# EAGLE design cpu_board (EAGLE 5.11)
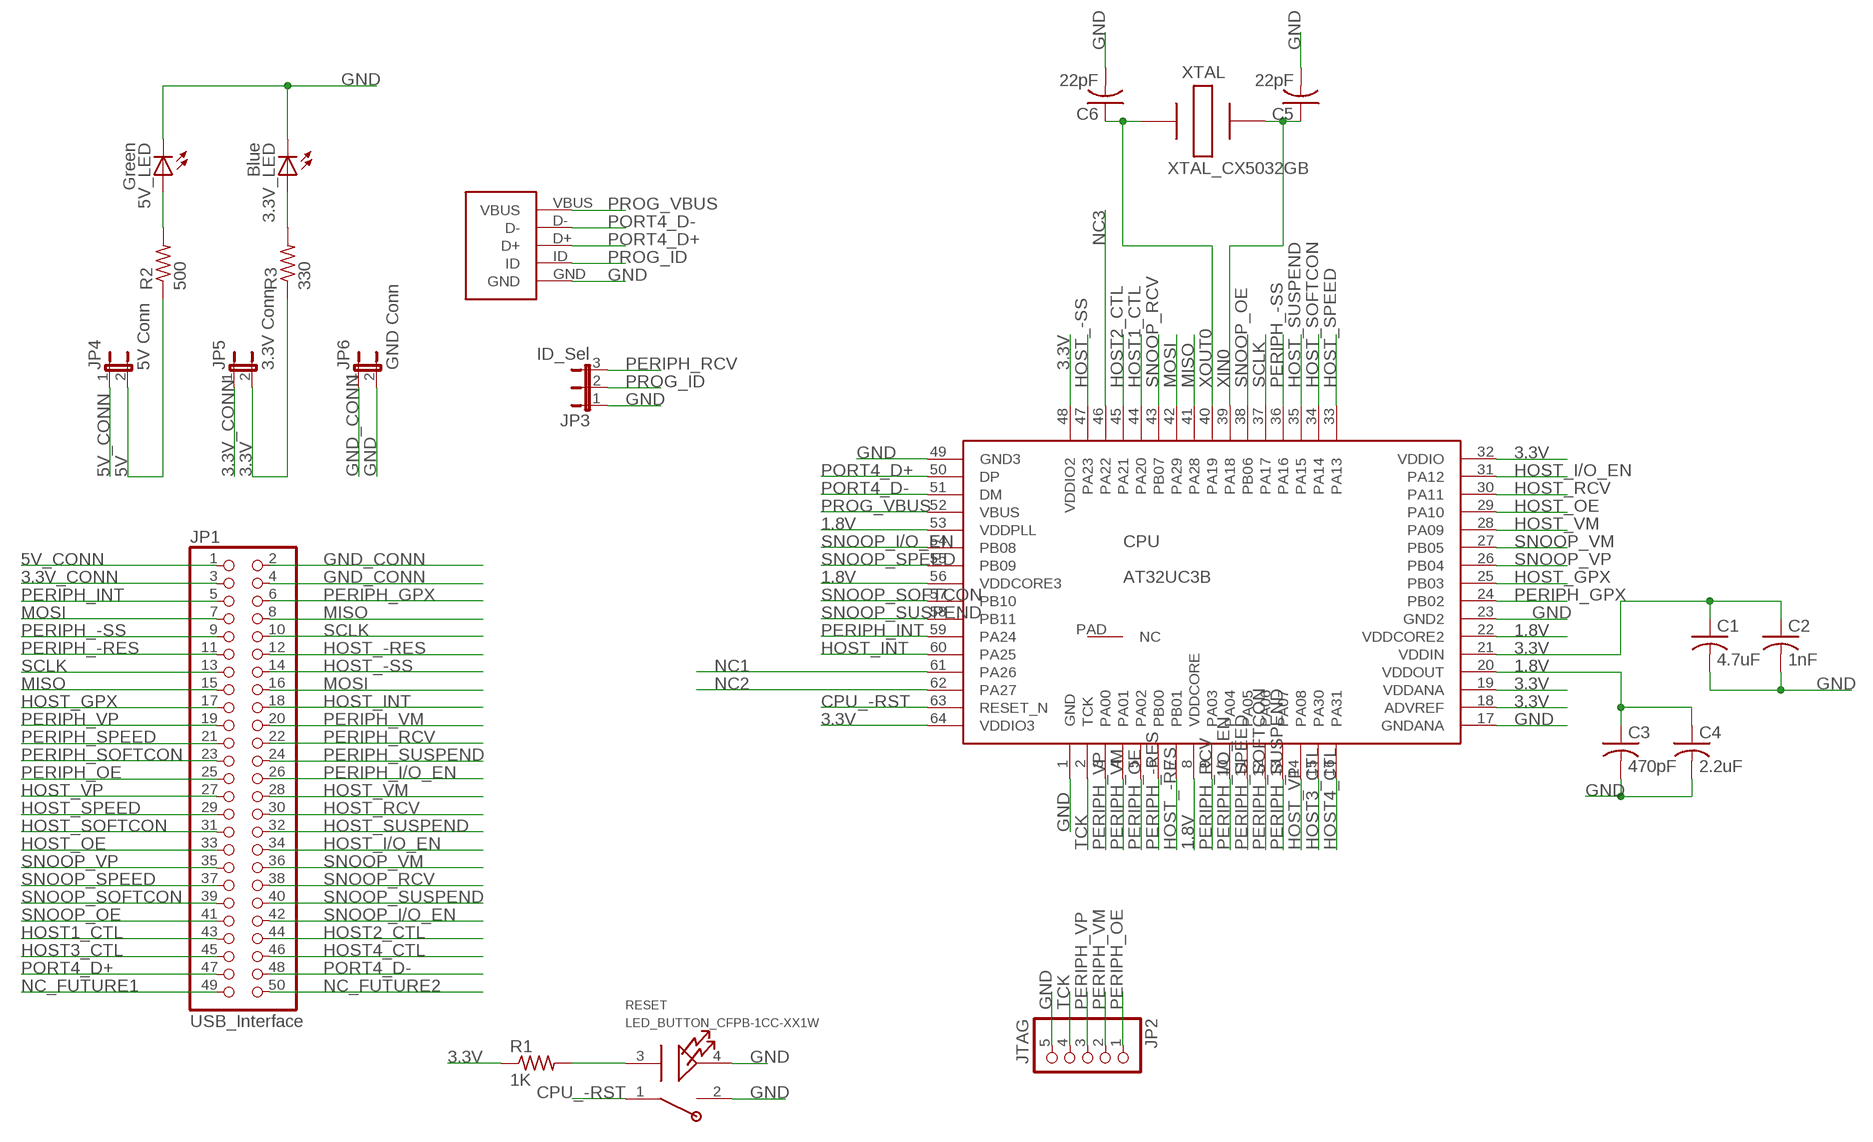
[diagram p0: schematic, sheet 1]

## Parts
3.3V_LED  Blue  LEDCHIP-LED0805  [CHIP-LED0805]
5V_LED  Green  LEDCHIP-LED0805  [CHIP-LED0805]
C1  4.7uF  C-USC0805  [C0805]
C2  1nF  C-USC0805  [C0805]
C3  470pF  C-USC0805  [C0805]
C4  2.2uF  C-USC0805  [C0805]
C5  22pF  C-USC0805  [C0805]
C6  22pF  C-USC0805  [C0805]
CPU  AT32UC3B  [QFN-64]
JP1  USB_Interface  PINHD-2X25/90  [2X25/90]
JP2  JTAG  PINHD-1X5  [1X05]
JP3  ID_Sel  JP2E  [JP2]
JP4  5V Conn  JP1E  [JP1]
JP5  3.3V Conn  JP1E  [JP1]
JP6  GND Conn  JP1E  [JP1]
R1  1K  R-US_R0805  [R0805]
R2  500  R-US_R0805  [R0805]
R3  330  R-US_R0805  [R0805]
RESET  LED_BUTTON_CFPB-1CC-XX1W  [CFPB-1CC-XX6W]
U$2  USB_MICRO_B_FEMALE  [USB_MICRO_B_FEMALE]
U$3  XTAL_CX5032GB  [CX5032GB]

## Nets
1.8V: C3.1 C4.1 CPU.8(VDDCORE) CPU.20(VDDOUT) CPU.22(VDDCORE2) CPU.53(VDDPLL) CPU.56(VDDCORE3)
3.3V: C1.1 C2.1 CPU.18(ADVREF) CPU.19(VDDANA) CPU.21(VDDIN) CPU.32(VDDIO) CPU.48(VDDIO2) CPU.64(VDDIO3) JP5.2 R1.1 R3.1
3.3V_CONN: JP1.3 JP5.1
5V: JP4.2 R2.1
5V_CONN: JP1.1 JP4.1
CPU_-RST: CPU.63(RESET_N) RESET.1(S1)
GND: 3.3V_LED.C 5V_LED.C C1.2 C2.2 C3.2 C4.2 C5.2 C6.2 CPU.1(GND) CPU.17(GNDANA) CPU.23(GND2) CPU.49(GND3) JP2.5 JP3.1 JP6.2 RESET.2(S2) RESET.4(K) U$2.GND
GND_CONN: JP1.2 JP1.4 JP6.1
HOST1_CTL: CPU.44(PA20) JP1.43
HOST2_CTL: CPU.45(PA21) JP1.44
HOST3_CTL: CPU.15(PA30) JP1.45
HOST4_CTL: CPU.16(PA31) JP1.46
HOST_-RES: CPU.7(PB01) JP1.12
HOST_-SS: CPU.47(PA23) JP1.14
HOST_GPX: CPU.25(PB03) JP1.17
HOST_I/O_EN: CPU.31(PA12) JP1.34
HOST_INT: CPU.60(PA25) JP1.18
HOST_OE: CPU.29(PA10) JP1.33
HOST_RCV: CPU.30(PA11) JP1.30
HOST_SOFTCON: CPU.34(PA14) JP1.31
HOST_SPEED: CPU.33(PA13) JP1.29
HOST_SUSPEND: CPU.35(PA15) JP1.32
HOST_VM: CPU.28(PA09) JP1.28
HOST_VP: CPU.14(PA08) JP1.27
MISO: CPU.41(PA28) JP1.8 JP1.15
MOSI: CPU.42(PA29) JP1.7 JP1.16
N$1: 5V_LED.A R2.2
N$2: R1.2 RESET.3(A)
N$4: 3.3V_LED.A R3.2
NC1: CPU.61(PA26)
NC2: CPU.62(PA27)
NC3: CPU.46(PA22)
NC_FUTURE1: JP1.49
NC_FUTURE2: JP1.50
PERIPH_-RES: CPU.6(PB00) JP1.11
PERIPH_-SS: CPU.36(PA16) JP1.9
PERIPH_GPX: CPU.24(PB02) JP1.6
PERIPH_I/O_EN: CPU.10(PA04) JP1.26
PERIPH_INT: CPU.59(PA24) JP1.5
PERIPH_OE: CPU.5(PA02) JP1.25 JP2.1
PERIPH_RCV: CPU.9(PA03) JP1.22 JP3.3
PERIPH_SOFTCON: CPU.12(PA06) JP1.23
PERIPH_SPEED: CPU.11(PA05) JP1.21
PERIPH_SUSPEND: CPU.13(PA07) JP1.24
PERIPH_VM: CPU.4(PA01) JP1.20 JP2.2
PERIPH_VP: CPU.3(PA00) JP1.19 JP2.3
PORT4_D+: CPU.50(DP) JP1.47 U$2.D+
PORT4_D-: CPU.51(DM) JP1.48 U$2.D-
PROG_ID: JP3.2 U$2.ID
PROG_VBUS: CPU.52(VBUS) U$2.VBUS
SCLK: CPU.37(PA17) JP1.10 JP1.13
SNOOP_I/O_EN: CPU.54(PB08) JP1.42
SNOOP_OE: CPU.38(PB06) JP1.41
SNOOP_RCV: CPU.43(PB07) JP1.38
SNOOP_SOFTCON: CPU.57(PB10) JP1.39
SNOOP_SPEED: CPU.55(PB09) JP1.37
SNOOP_SUSPEND: CPU.58(PB11) JP1.40
SNOOP_VM: CPU.27(PB05) JP1.36
SNOOP_VP: CPU.26(PB04) JP1.35
TCK: CPU.2(TCK) JP2.4
XIN0: C5.1 CPU.39(PA18) U$3.P$2
XOUT0: C6.1 CPU.40(PA19) U$3.P$1
Unconnected: CPU.PAD(NC)

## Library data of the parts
3.3V_LED 5V_LED = led:LED: LED
C1-C6 = resistor:C-US: CAPACITOR, American symbol
CPU = cpu_stuff:AT32UC3B
JP1 = pinhead:PINHD-2X25: PIN HEADER
JP2 = pinhead:PINHD-1X5: PIN HEADER
JP3 = jumper:JP2E: JUMPER
JP4-JP6 = jumper:JP1E: JUMPER
R1 = resistor:R-US_: RESISTOR, American symbol
R2 R3 = rcl:R-US_: RESISTOR, American symbol
RESET = cpu_stuff:LED_BUTTON_CFPB-1CC-XX1W
U$2 = usb:USB_MICRO_B_FEMALE
U$3 = cpu_stuff:XTAL_CX5032GB

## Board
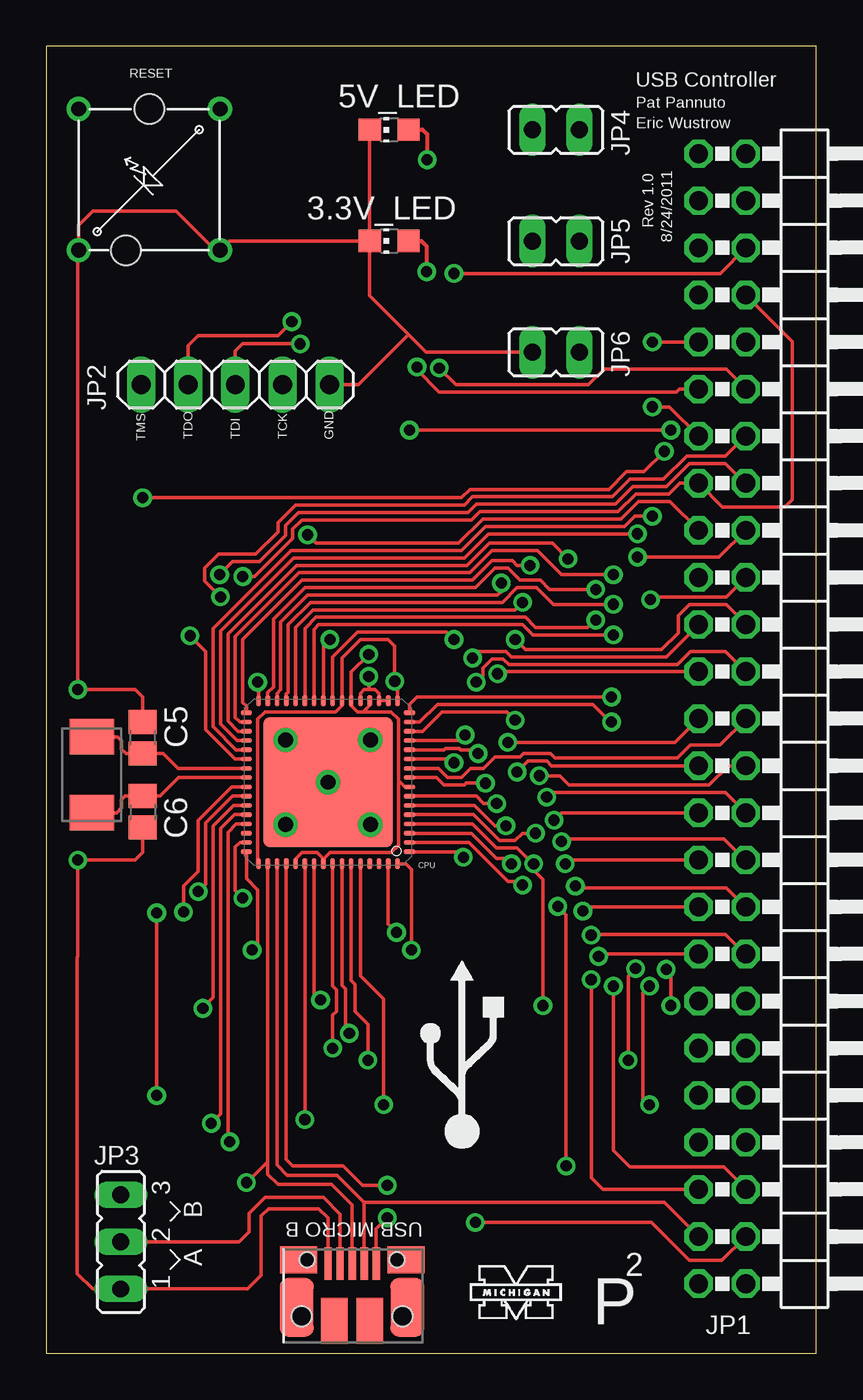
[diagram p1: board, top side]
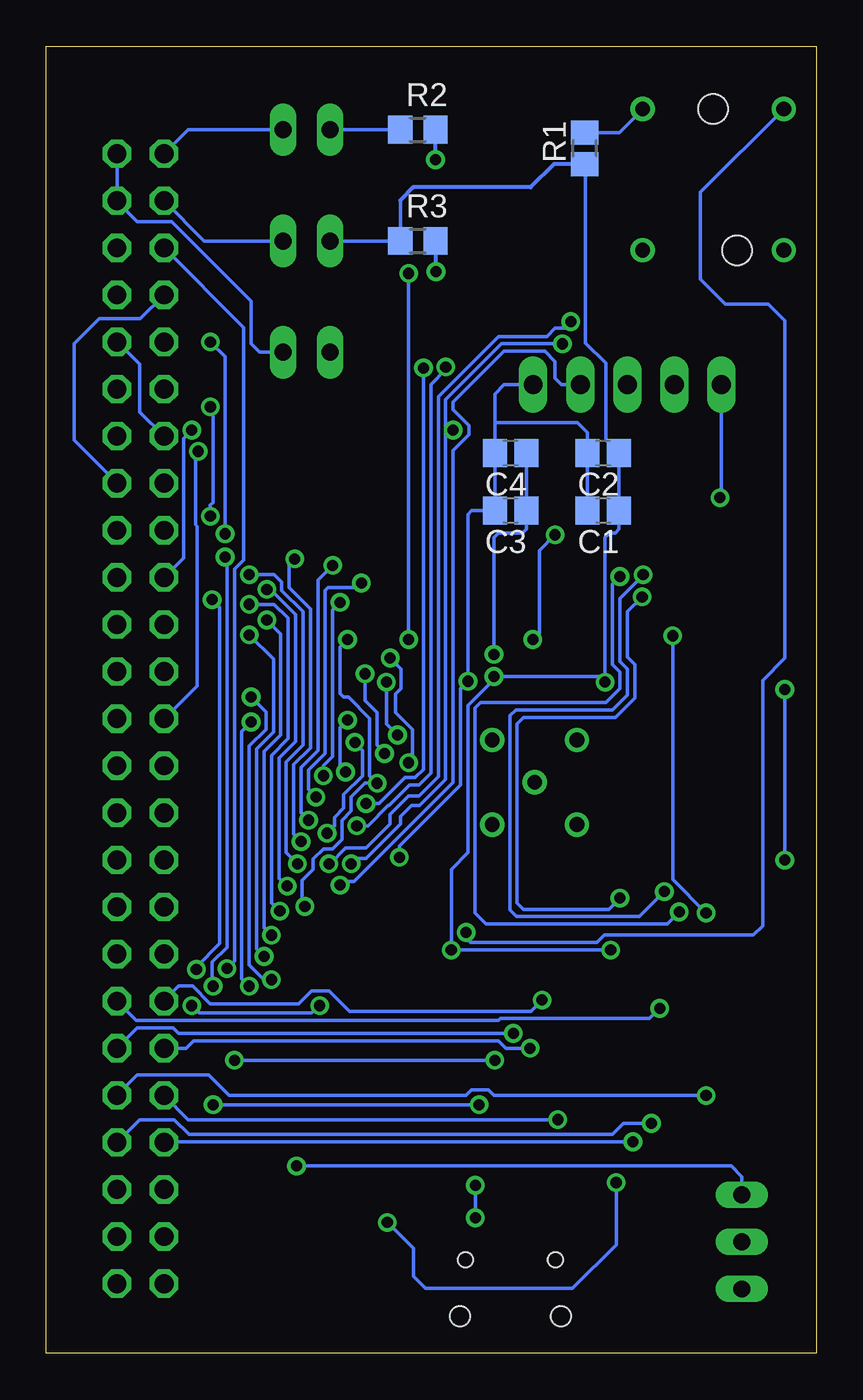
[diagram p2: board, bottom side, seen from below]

Size 41.55 x 70.5 mm. Coordinates in mm from the lower left corner, seen from the top.
Outline: 0,0 41.55,0 41.55,70.5 0,70.5 0,0
Copper layers (1*16): Top 0.035mm / dielectric 1.5mm / Bottom 0.035mm
Design rules "default *": minimum track width 7mil, minimum drill 16mil, track to track 7mil, track to pad 7mil, pad to pad 7mil, via to via 7mil, smd to smd 7mil, copper to edge 40mil, drill to drill 8mil, minimum pad ring 10mil, minimum via ring 8mil, stop-mask expansion 4mil, vias tented up to drill 0mil, thermal gap 10mil

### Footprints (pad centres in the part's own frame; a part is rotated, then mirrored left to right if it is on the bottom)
CHIP-LED0805 = smd 1.2 x 1.2: A 0,-1.05; C 0,1.05
C0805 = smd 1.3 x 1.5: 1 -0.85,0; 2 0.85,0
QFN-64 = smd 0.6 x 0.25: 1 -4.4,3.75; 2 -4.4,3.25; 3 -4.4,2.75; 4 -4.4,2.25; 5 -4.4,1.75; 6 -4.4,1.25; 7 -4.4,0.75; 8 -4.4,0.25; 9 -4.4,-0.25; 10 -4.4,-0.75; 11 -4.4,-1.25; 12 -4.4,-1.75; 13 -4.4,-2.25; 14 -4.4,-2.75; 15 -4.4,-3.25; 16 -4.4,-3.75; 33 4.4,-3.75; 34 4.4,-3.25; 35 4.4,-2.75; 36 4.4,-2.25; 37 4.4,-1.75; 38 4.4,-1.25; 39 4.4,-0.75; 40 4.4,-0.25; 41 4.4,0.25; 42 4.4,0.75; 43 4.4,1.25; 44 4.4,1.75; 45 4.4,2.25; 46 4.4,2.75; 47 4.4,3.25; 48 4.4,3.75 | smd 0.25 x 0.6: 17 -3.75,-4.4; 18 -3.25,-4.4; 19 -2.75,-4.4; 20 -2.25,-4.4; 21 -1.75,-4.4; 22 -1.25,-4.4; 23 -0.75,-4.4; 24 -0.25,-4.4; 25 0.25,-4.4; 26 0.75,-4.4; 27 1.25,-4.4; 28 1.75,-4.4; 29 2.25,-4.4; 30 2.75,-4.4; 31 3.25,-4.4; 32 3.75,-4.4; 49 3.75,4.4; 50 3.25,4.4; 51 2.75,4.4; 52 2.25,4.4; 53 1.75,4.4; 54 1.25,4.4; 55 0.75,4.4; 56 0.25,4.4; 57 -0.25,4.4; 58 -0.75,4.4; 59 -1.25,4.4; 60 -1.75,4.4; 61 -2.25,4.4; 62 -2.75,4.4; 63 -3.25,4.4; 64 -3.75,4.4 | drill 0.8 round: P$1 -2.286,2.286; P$3 -2.286,-2.286; P$4 2.286,-2.286; P$6 2.286,2.286; P$8 0,0 | smd 7 x 7: PAD 0,0
2X25/90 = drill 1.016 octagon: 1 -29.21,-6.35; 2 -29.21,-3.81; 3 -26.67,-6.35; 4 -26.67,-3.81; 5 -24.13,-6.35; 6 -24.13,-3.81; 7 -21.59,-6.35; 8 -21.59,-3.81; 9 -19.05,-6.35; 10 -19.05,-3.81; 11 -16.51,-6.35; 12 -16.51,-3.81; 13 -13.97,-6.35; 14 -13.97,-3.81; 15 -11.43,-6.35; 16 -11.43,-3.81; 17 -8.89,-6.35; 18 -8.89,-3.81; 19 -6.35,-6.35; 20 -6.35,-3.81; 21 -3.81,-6.35; 22 -3.81,-3.81; 23 -1.27,-6.35; 24 -1.27,-3.81; 25 1.27,-6.35; 26 1.27,-3.81; 27 3.81,-6.35; 28 3.81,-3.81; 29 6.35,-6.35; 30 6.35,-3.81; 31 8.89,-6.35; 32 8.89,-3.81; 33 11.43,-6.35; 34 11.43,-3.81; 35 13.97,-6.35; 36 13.97,-3.81; 37 16.51,-6.35; 38 16.51,-3.81; 39 19.05,-6.35; 40 19.05,-3.81; 41 21.59,-3.81; 42 21.59,-6.35; 43 24.13,-3.81; 44 24.13,-6.35; 45 26.67,-3.81; 46 26.67,-6.35; 47 29.21,-3.81; 48 29.21,-6.35; 49 31.75,-3.81; 50 31.75,-6.35
1X05 = drill 1.016 long: 1 -5.08,0; 2 -2.54,0; 3 0,0; 4 2.54,0; 5 5.08,0
JP2 = drill 0.914 long: 1 -2.54,0; 2 0,0; 3 2.54,0
JP1 = drill 0.914 long: 1 0,-1.27; 2 0,1.27
R0805 = smd 1.3 x 1.5: 1 -0.85,0; 2 0.85,0
R0805' = smd 1.3 x 1.5: 1 -0.95,0; 2 0.95,0
CFPB-1CC-XX6W = drill 0.8 pad 1.016 round: 1 0,7.62; 2 7.62,0; 3 7.62,7.62; 4 0,0 | hole 1.6: 2.54,0; 3.81,7.62
USB_MICRO_B_FEMALE = smd 0.4 x 1.75: D+ 0,2.825; D- 0.65,2.825; GND -1.3,2.825; ID -0.65,2.825; VBUS 1.3,2.825 | smd 1.425 x 2.5: P$6 0.963,-0.25; P$7 -0.963,-0.25 | smd 2 x 1.46: P$8 2.9,3.03; P$9 -2.9,3.03 | smd 1.825 x 3.15: P$10 2.987,0.475; P$11 -2.987,0.475 | hole 0.828: 2.425,3.03; -2.425,3.03 | hole 1.081: 2.725,0; -2.725,0
CX5032GB = smd 1.9 x 2.4: P$1 -2.05,0; P$2 2.05,0

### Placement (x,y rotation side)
3.3V_LED  18.5,60 90 top
5V_LED  18.5,66 90 top
C1  11.5,45.45 180 bottom
C2  11.5,48.55 180 bottom
C3  16.5,45.45 180 bottom
C4  16.5,48.55 180 bottom
C5  5.2,33.2 90 top
C6  5.2,29.2 270 top
CPU  15.2,30.8 180 top
JP1  41.55,35.5 270 top
JP2  10.2,52.25 0 top
JP3  4.02,6 90 top
JP4  27.5,66 90 top
JP5  27.5,60 90 top
JP6  27.5,54 90 top
R1  12.5,65 90 bottom
R2  500  [R0805']  21.5,66 0 bottom
R3  330  [R0805']  21.5,60 0 bottom
RESET  1.75,59.5 0 top
U$2  16.5,2 0 top
U$3  2.45,31.2 90 top

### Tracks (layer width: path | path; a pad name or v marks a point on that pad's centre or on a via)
1.8V  (via drill 0.6)
  Top 0.178: CPU.53 13.45,26.65 13.8,27 14.6,27 14.95,26.65 | CPU.56 14.95,26.65 | 17.15,34.65 17.45,34.95 CPU.20 | 17.15,34.65 17.1,34.6 16.8,34.6 16.45,34.95 CPU.22 16.45,36.75 v17.4,37.7 | CPU.8 19.35,30.55 19.05,30.85 | 19.05,30.85 19,30.9 19,34.2 18.6,34.6 17.2,34.6 17.15,34.65 | 14.95,26.65 15.3,27 18.6,27 19,27.4 19,30.8 19.05,30.85
  Bottom 0.178: C4.1 C3.1 15.65,44.45 15.85,44.25 17.15,44.25 17.4,44 v17.4,37.7
3.3V  (via drill 0.6)
  Top 0.178: CPU.64 19.4,26.4 19.7,26.1 v19.7,21.75 | CPU.32 11.45,36.15 v11.4,36.2 | CPU.18 CPU.19 17.95,35.6 17.75,35.8 17.4,35.8 | 17.4,35.8 17.15,35.8 16.95,35.6 CPU.21 | CPU.48 10.8,25.6 11.4,25 11.4,22.05 v11.1,21.75 | v17.4,36.5 17.4,35.8
  Bottom 0.178: JP5.2 R3.1 22.45,62.2 | R1.1 12.45,64.1 12.45,54.5 11.35,53.4 11.35,49.25 C2.1 C1.1 10.65,44.45 10.85,44.25 11.15,44.25 11.4,44 v11.4,36.2 11.7,36.5 v17.4,36.5 17.4,36.35 18.8,34.95 18.8,27 19.7,26.1 v19.7,21.75 v11.1,21.75
  Bottom 0.203: 22.45,62.2 21.76,62.89 15.42,62.89 14.16,64.15 R1.1
3.3V_CONN
  Bottom 0.178: JP1.3 33.03,60 JP5.1
5V
  Bottom 0.178: R2.1 JP4.2
5V_CONN
  Bottom 0.178: JP1.1 33.91,66 JP4.1
CPU_-RST  (via drill 0.6)
  Top 0.178: CPU.63 18.45,23.15 v18.9,22.7
  Bottom 0.178: v18.9,22.7 18.9,22.4 18.65,22.15 11.85,22.15 11.45,22.55 3.4,22.55 2.9,23.05 2.9,36.3 1.7,37.5 1.7,55.7 2.6,56.6 4.9,56.6 6.25,57.95 6.25,62.62 RESET.1
GND  (via drill 0.6)
  Top 0.178: 3.3V_LED.C 5V_LED.C | 3.3V_LED.C 9.87,60 RESET.2 9.1,59.5 7,61.6 2.5,61.6 1.75,60.85 RESET.4 1.7,59.45 v1.7,35.8 4.8,35.8 5.2,35.4 C5.2 | JP6.2 20.5,54 19.55,54.95 | 19.55,54.95 17.45,57.05 3.3V_LED.C | C6.2 5.2,27 4.8,26.6 v1.7,26.6 1.7,21.4 1.68,21.38 1.68,4.29 2.5,3.46 3.5,3.46 JP3.1 10.86,3.46 11.6,4.2 11.6,7.4 12,7.8 14.7,7.8 15.2,7.3 U$2.GND | CPU.49 11.4,26.45 11.4,34.2 11.8,34.6 15.6,34.6 15.95,34.95 CPU.23 15.95,37.5 16.95,38.5 18.45,38.5 18.8,38.15 v18.8,36.25 18.95,36.1 CPU.17 | JP2.5 16.85,52.25 19.55,54.95 | CPU.1 22.2,27.05 v22.5,26.75
  Bottom 0.178: v1.7,26.6 v1.7,35.8 | 17.35,50.2 17.35,51.75 16.85,52.25 JP2.5 | 17.35,50.2 C4.2 C3.2 18.6,45.45 18.8,45.25 v18.8,36.25 19.2,35.85 19.2,30.65 22.5,27.35 v22.5,26.75 | C1.2 C2.2 12.35,49.65 12.9,50.2 17.35,50.2
GND_CONN
  Bottom 0.178: JP1.2 JP1.4 37.74,62.14 36.65,61.05 34.8,61.05 30.5,56.75 30.5,54.45 30.05,54 JP6.1
HOST1_CTL  (via drill 0.6)
  Top 0.178: CPU.44 10.15,29.05 9.4,28.3 9.4,12.9 v8.9,12.4
  Bottom 0.178: v8.9,12.4 10.4,12.4 11,11.8 33.85,11.8 34.65,12.6 36.51,12.6 JP1.43
HOST2_CTL  (via drill 0.6)
  Top 0.178: CPU.45 10.25,28.55 9.8,28.1 9.8,11.5 v9.9,11.4
  Bottom 0.178: v9.9,11.4 35.17,11.4 JP1.44
HOST3_CTL  (via drill 0.6)
  Top 0.178: JP1.45 37.74,8.86 36.55,10.05 31.5,10.05 30.6,10.95 v30.6,19.8 | v30.5,34.05 30.45,34.05 29.5,35 21.1,35 20.15,34.05 CPU.15
  Bottom 0.178: v30.5,34.05 31,33.55 31,20.2 v30.6,19.8
HOST4_CTL  (via drill 0.6)
  Top 0.178: CPU.16 19.6,35 20,35.4 v30.5,35.4 | v29.4,20.15 29.4,9.45 30.02,8.83 JP1.46
  Bottom 0.178: v30.5,35.4 29.7,34.6 29.7,33.65 30.6,32.75 30.6,20.95 29.8,20.15 v29.4,20.15
HOST_-RES  (via drill 0.6)
  Top 0.178: CPU.7 23.2,30.05 23.6,29.65 v24.3,29.65 | JP1.12 37.74,52.06 36.7,53.1 30.1,53.1 29.25,52.25 22.1,52.25 v21.2,53.15
  Bottom 0.178: v24.3,29.65 23.6,29.65 22.2,31.05 21.65,31.05 21.2,31.5 v21.2,53.15
HOST_-SS  (via drill 0.6)
  Top 0.178: CPU.47 10.45,27.55 10.2,27.3 10.2,24.95 v10.6,24.55 | JP1.14 37.72,49.47 36.65,48.4 34.55,48.4 33.3,47.15 31.5,47.15 30.55,46.2 23,46.2 22.55,45.75 13.45,45.75 12.5,44.8 12.5,44.3 11.3,43.1 9.3,43.1 8.55,42.35 8.55,41.65 v9.4,40.8
  Bottom 0.178: v9.4,40.8 10.2,40 10.2,37.55 9.8,37.15 9.8,35.35 10.85,34.3 15.8,34.3 16.15,33.95 16.15,24.3 15.8,23.95 11.2,23.95 v10.6,24.55
HOST_GPX  (via drill 0.6)
  Top 0.178: JP1.17 33.65,45.95 31.95,45.95 31,45 23.55,45 22.25,43.7 14.55,43.7 v14.1,44.15 | v15.3,38.5 14.95,38.15 CPU.25
  Bottom 0.178: v14.1,44.15 14.95,43.3 14.95,38.85 v15.3,38.5
HOST_I/O_EN  (via drill 0.6)
  Top 0.178: JP1.34 36.7,25.1 28.65,25.1 v28.55,25.2 | v29.65,41.2 27.15,41.2 26.65,41.7 25.55,41.7 24.9,42.35 24.2,42.35 23.15,41.3 13.95,41.3 12.25,39.6 12.25,35.95 11.95,35.65 CPU.31
  Bottom 0.178: v28.55,25.2 28.6,25.2 29,25.6 29,32.1 28.1,33 28.1,39.85 29.45,41.2 v29.65,41.2
HOST_INT  (via drill 0.6)
  Top 0.178: CPU.60 16.95,20.35 18.2,19.1 v18.2,13.4 | v32.55,13.4 32.5,13.4 32.2,13.7 32.2,19.45 v32.55,19.8 | v31.9,42.95 36.3,42.95 JP1.18
  Bottom 0.178: v18.2,13.4 v32.55,13.4 | v31.9,42.95 31.8,42.85 31.8,21.9 32.6,21.1 32.6,19.85 v32.55,19.8
HOST_OE  (via drill 0.6)
  Top 0.178: JP1.33 29.17,24.07 v28.95,23.85 | v30.6,40.4 27.35,40.4 26.45,41.3 25.4,41.3 24.6,40.5 14.25,40.5 13.05,39.3 13.05,35.65 12.95,35.55 CPU.29
  Bottom 0.178: v28.95,23.85 29.4,24.3 29.4,32.25 28.5,33.15 28.5,39.65 29.25,40.4 v30.6,40.4
HOST_RCV  (via drill 0.6)
  Top 0.178: JP1.30 36.65,30.25 27.25,30.25 v27,30 | v24.55,41.55 24.55,41.1 24.35,40.9 14.1,40.9 12.65,39.45 12.65,35.8 12.45,35.6 CPU.30
  Bottom 0.178: v27,30 27.4,30.4 27.4,31.45 26.5,32.35 26.5,41.15 26.35,41.3 24.8,41.3 v24.55,41.55
HOST_SOFTCON  (via drill 0.6)
  Top 0.178: CPU.34 10.45,34.05 10.2,34.3 10.2,38.65 13.65,42.1 22.85,42.1 24.05,43.3 26.5,43.3 27.8,42 v30.6,42 | JP1.31 28.21,26.61 v28,26.4
  Bottom 0.178: v28,26.4 28.6,27 28.6,31.9 27.7,32.8 27.7,40 28.85,41.15 28.85,41.6 29.25,42 v30.6,42 | JP1.31
HOST_SPEED  (via drill 0.6)
  Top 0.178: CPU.33 10.8,34.9 10.6,35.1 10.6,38.5 13.8,41.7 23,41.7 24.05,42.75 25.15,42.75 25.4,42.5 v26.1,42.5 | JP1.29 27.8,29.15 v27.4,28.75
  Bottom 0.178: v27.4,28.75 27.8,29.15 27.8,31.6 26.9,32.5 26.9,41.7 v26.1,42.5
HOST_SUSPEND  (via drill 0.6)
  Top 0.178: CPU.35 10.35,33.55 9.8,34.1 9.8,38.8 13.5,42.5 22.7,42.5 23.9,43.7 27.3,43.7 v28.15,42.85 | JP1.32 37.69,26.61 36.55,27.75 27.95,27.75 v27.8,27.6
  Bottom 0.178: v27.8,27.6 28.2,28 28.2,31.75 27.3,32.65 27.3,40.15 28.45,41.3 28.45,42.55 v28.15,42.85
HOST_VM  (via drill 0.6)
  Top 0.178: JP1.28 36.79,31.69 35.75,30.65 28.2,30.65 27.7,31.15 v26.6,31.15 | v25.7,40.5 25.3,40.1 14.4,40.1 13.45,39.15 CPU.28
  Bottom 0.178: v26.6,31.15 26.6,31.7 26.1,32.2 26.1,40.1 v25.7,40.5
HOST_VP  (via drill 0.6)
  Top 0.178: JP1.27 27.26,31.69 27,31.95 26,31.95 v25.4,31.35 | v25.3,34.15 24.85,34.6 21.35,34.6 20.3,33.55 CPU.14
  Bottom 0.178: v25.3,34.15 25.7,33.75 25.7,31.65 v25.4,31.35
MISO  (via drill 0.6)
  Top 0.178: CPU.41 10,30.55 8.2,28.75 8.2,26 7.4,25.2 v7.4,23.8 | v10.6,41.9 11.25,41.9 13.3,43.95 13.3,44.45 13.8,44.95 22.95,44.95 23.4,45.4 30.85,45.4 31.8,46.35 33.6,46.35 34.18,46.93 JP1.15 36.48,45.65 39.85,45.65 40.25,46.05 40.25,54.58 JP1.8
  Bottom 0.178: v10.6,41.9 11,41.5 11,37.15 10.6,36.75 10.6,35.85 11.35,35.1 18.12,35.1 18.42,34.8 18.42,23.75 17.82,23.15 8.05,23.15 v7.4,23.8
MOSI  (via drill 0.6)
  Top 0.178: CPU.42 10.05,30.05 8.6,28.6 8.6,25.3 v8.2,24.9 | JP1.16 37.72,46.93 36.65,48 34.7,48 33.45,46.75 31.65,46.75 30.7,45.8 23.2,45.8 22.75,45.35 13.6,45.35 12.9,44.65 12.9,44.1 11.5,42.7 10.05,42.7 v9.35,42
  Bottom 0.178: v9.35,42 9.35,41.95 10.6,40.7 10.6,37.3 10.2,36.9 10.2,35.5 11,34.7 16.22,34.7 16.52,34.4 16.52,23.9 16.17,23.55 9.55,23.55 v8.2,24.9 | JP1.16 40.05,49.25 40.05,54.45 38.7,55.8 36.49,55.8 JP1.7
N$1  (via drill 0.6)
  Top 0.203: v20.55,64.39 20.55,65.76 20.3,66.02 19.57,66.02 5V_LED.A
  Bottom 0.203: R2.2 v20.55,64.39
N$2
  Bottom 0.178: RESET.3 10.64,65.85 R1.2
N$4  (via drill 0.6)
  Top 0.203: v20.52,58.34 20.52,59.72 20.24,60 3.3V_LED.A
  Bottom 0.203: R3.2 20.52,59.97 v20.52,58.34
PERIPH_-RES  (via drill 0.6)
  Top 0.178: CPU.6 23.1,29.55 24.2,28.45 v24.8,28.45 | v20,53.2 20,53.05 21.2,51.85 34,51.85 34.15,52 JP1.11
  Bottom 0.178: v24.8,28.45 24.2,28.45 23.1,29.55 23.05,29.55 21.95,30.65 21.45,30.65 20.8,31.3 20.8,52.25 20,53.05 v20,53.2
PERIPH_-SS  (via drill 0.6)
  Top 0.178: CPU.36 10.3,33.05 9.4,33.95 9.4,38.95 13.35,42.9 22.55,42.9 23.85,44.2 v31.9,44.2 | v32.7,54.55 JP1.9
  Bottom 0.178: v31.9,44.2 31.9,53.75 v32.7,54.55
PERIPH_GPX  (via drill 0.6)
  Top 0.178: CPU.24 15.45,37.55 16.8,38.9 21.6,38.9 v22,38.5 | v22,58.25 36.36,58.25 JP1.6
  Bottom 0.178: v22,38.5 v22,58.25
PERIPH_I/O_EN
  Top 0.178: JP1.26 37.74,34.19 36.35,32.8 34.75,32.8 34.05,32.1 27.45,32.1 27.2,32.35 25.75,32.35 25.55,32.15 24.2,32.15 23.6,31.55 22.9,31.55 22.4,31.05 21.65,31.05 21.15,31.55 CPU.10
PERIPH_INT  (via drill 0.6)
  Top 0.178: CPU.59 16.45,20.1 16.65,19.9 16.65,18.45 17.35,17.75 v17.35,15.8 | v31.4,15.8 31.4,20.35 v31.8,20.75
  Bottom 0.178: v17.35,15.8 v31.4,15.8 | v31.8,20.75 31.4,21.15 31.4,42.3 30.9,42.8 30.9,55.33 JP1.5
PERIPH_OE  (via drill 0.6)
  Top 0.178: v24.9,32.95 33.92,32.95 JP1.25 | CPU.5 23.05,29.05 24.45,27.65 25.3,27.65 25.7,28.05 v26.4,28.05 | v33.35,48.65 32.25,47.55 31.3,47.55 30.35,46.6 22.85,46.6 22.4,46.15 v5.2,46.15
  Bottom 0.178: v24.9,32.95 24.9,32.9 24.5,32.5 24.5,31.15 25.5,30.15 25.5,29.4 26,28.9 26,28.45 v26.4,28.05 | JP1.25 35.17,34.23 33.4,36 33.4,44.6 33.5,44.7 33.5,48.5 v33.35,48.65 | v5.2,46.15 5.12,46.23 JP2.1
PERIPH_RCV  (via drill 0.6)
  Top 0.178: JP1.22 37.74,39.36 36.7,40.4 34.7,40.4 34.1,39.8 34.1,38.85 33.2,37.95 25.85,37.95 v25.3,38.5 | v23.7,30.75 22.65,30.75 22.55,30.65 21.45,30.65 21.05,31.05 CPU.9 | v27.6,24.1 28.05,23.65 v28.05,10.1
  Bottom 0.178: v27.6,24.1 27.75,24.25 27.75,25.5 27.15,26.1 27.15,26.65 26.6,27.2 26.1,27.2 25.6,27.7 25.6,28.75 25.1,29.25 25.1,30 24.35,30.75 v23.7,30.75 24.1,31.15 24.1,34.25 25.25,35.4 25.5,35.4 25.7,35.6 25.7,38.1 v25.3,38.5 | v28.05,10.1 4.6,10.1 4.02,9.52 JP3.3
PERIPH_SOFTCON  (via drill 0.6)
  Top 0.178: JP1.23 24.47,36.77 v24.35,36.65 | v23.3,32.35 23.1,32.55 22.36,32.55 22.29,32.62 21.54,32.62 21.47,32.55 CPU.12
  Bottom 0.178: v23.3,32.35 23.3,32.4 23.7,32.8 23.7,34.55 24.35,35.2 v24.35,36.65
PERIPH_SPEED  (via drill 0.6)
  Top 0.178: JP1.21 33.45,37.55 25.1,37.55 24.8,37.85 23.35,37.85 v23,37.5 | CPU.11 21.8,32.05 v22,31.85
  Bottom 0.178: v22,31.85 21.8,32.05 21.8,33.65 22.7,34.55 22.7,35.55 22.4,35.85 22.4,36.9 v23,37.5
PERIPH_SUSPEND  (via drill 0.6)
  Top 0.178: JP1.24 36.65,37.85 34.75,37.85 34.05,37.15 24.95,37.15 24.65,37.45 24.05,37.45 23.55,36.95 23.55,36.55 v23.2,36.2 | v22.6,33.35 22.3,33.05 CPU.13
  Bottom 0.178: v22.6,33.35 23.2,33.95 v23.2,36.2
PERIPH_VM  (via drill 0.6)
  Top 0.178: CPU.4 23,28.55 24.3,27.25 25.4,27.25 26.25,26.4 v26.3,26.4 26.3,26.05 26.8,25.55 v26.8,18.75 | v33.7,18.75 33.7,20.45 v33.45,20.7 | v32.6,40.65 32.75,40.8 36.69,40.8 JP1.20 | v13.25,55.65 12.5,54.9 8.2,54.9 7.66,54.36 JP2.2
  Bottom 0.178: v26.3,26.4 26.25,26.4 25.4,27.25 24.3,27.25 23,28.55 23,29.05 22,30.05 21.45,30.05 20.4,31.1 20.4,51.6 17.15,54.85 14.55,54.85 14.1,55.3 13.6,55.3 v13.25,55.65 | v26.8,18.75 26.85,18.75 27.25,18.35 33.3,18.35 v33.7,18.75 | v33.45,20.7 33.45,20.85 32.2,22.1 32.2,40.25 v32.6,40.65
PERIPH_VP  (via drill 0.6)
  Top 0.178: CPU.3 22.95,28.05 24.3,26.7 24.8,26.7 v25.1,26.4 | v13.7,54.45 10.6,54.45 10.2,54.05 JP2.3 | v19.6,49.8 v33.7,49.8
  Bottom 0.178: v25.1,26.4 24.8,26.7 24.3,26.7 22.45,28.55 22.45,28.95 21.85,29.55 21.4,29.55 20,30.95 20,49.8 | v13.7,54.45 17,54.45 20,51.45 20,49.8 | JP1.19 34.15,42.9 34.15,49.35 v33.7,49.8 | 20,49.8 v19.6,49.8
PORT4_D+  (via drill 0.6)
  Top 0.178: 11.95,10.3 11.95,9.65 12.5,9.1 15.4,9.1 16.5,8 U$2.D+ | 11.95,10.3 CPU.50 | JP1.47 36.45,5 34.7,5 32.65,7.05 v23.15,7.05 | v10.8,9.2 11.9,10.3 11.95,10.3
  Bottom 0.178: v10.8,9.2 10.8,5.85 13.15,3.5 21.1,3.5 21.75,4.15 21.75,5.65 v23.15,7.05
PORT4_D-
  Top 0.178: CPU.51 12.45,10.15 13,9.6 15.7,9.6 17.15,8.15 | U$2.D- 17.15,8.15 | JP1.48 33.34,8.15 17.15,8.15
PROG_ID
  Top 0.178: U$2.ID 15.85,7.5 14.95,8.4 11.8,8.4 10.95,7.55 10.95,6.55 10.4,6 JP3.2
PROG_VBUS  (via drill 0.6)
  Top 0.178: U$2.VBUS 17.8,6.7 v18.4,7.3 | CPU.52 12.95,10.45 13.3,10.1 16,10.1 17.05,9.05 v18.4,9.05
  Bottom 0.178: v18.4,7.3 v18.4,9.05
SCLK  (via drill 0.6)
  Top 0.178: CPU.37 10.25,32.55 9,33.8 9,39.1 13.2,43.3 22.4,43.3 23.7,44.6 31.2,44.6 31.75,45.15 v32.7,45.15 | v32.7,51.05 33.62,51.05 JP1.13
  Bottom 0.178: v32.7,45.15 32.7,45.75 32.55,45.9 32.55,50.9 v32.7,51.05 | JP1.10 37.7,54.55 36.5,53.35 36.5,50.77 JP1.13
SNOOP_I/O_EN  (via drill 0.6)
  Top 0.178: v13.95,12.6 CPU.54
  Bottom 0.178: JP1.42 33.89,12.6 v13.95,12.6
SNOOP_OE  (via drill 0.6)
  Top 0.178: CPU.38 10.2,32.05 8.6,33.65 8.6,37.85 v7.75,38.7 | v5.95,13.9 v5.95,23.75
  Bottom 0.178: v7.75,38.7 7.75,25.55 v5.95,23.75 | v5.95,13.9 17.4,13.9 17.7,14.2 18.6,14.2 18.9,13.9 31.7,13.9 32.8,15 36.65,15 JP1.41
SNOOP_RCV  (via drill 0.6)
  Top 0.178: CPU.43 10.1,29.55 9,28.45 9,19.2 8.45,18.65 v8.45,18.6
  Bottom 0.178: JP1.38 36.7,17.95 17.15,17.95 17.05,18.05 9,18.05 v8.45,18.6
SNOOP_SOFTCON  (via drill 0.6)
  Top 0.178: v15.45,16.45 15.45,18.25 15.65,18.45 15.65,19.6 15.45,19.8 CPU.57
  Bottom 0.178: v15.45,16.45 16.75,16.45 17.15,16.85 33.6,16.85 34,16.45 JP1.39
SNOOP_SPEED  (via drill 0.6)
  Top 0.178: CPU.55 14.45,19.4 v14.8,19.05
  Bottom 0.178: JP1.37 34.4,19.8 33.65,19.8 32.7,18.85 27.95,18.85 27.25,19.55 26.3,19.55 25.2,18.45 15.4,18.45 v14.8,19.05
SNOOP_SUSPEND  (via drill 0.6)
  Top 0.178: CPU.58 15.95,19.85 16.15,19.65 16.15,17.45 v16.35,17.25
  Bottom 0.178: JP1.40 36.64,17.55 34.7,17.55 34.4,17.25 v16.35,17.25
SNOOP_VM  (via drill 0.6)
  Top 0.178: JP1.36 37.72,21.53 36.65,22.6 29.45,22.6 v29.4,22.55 | v29.65,39.55 29.6,39.55 29.2,39.15 26.4,39.15 25.85,39.7 14.55,39.7 13.95,39.1 CPU.27
  Bottom 0.178: v29.4,22.55 29.8,22.95 29.8,32.45 28.9,33.35 28.9,38.8 v29.65,39.55
SNOOP_VP  (via drill 0.6)
  Top 0.178: JP1.35 29.93,21.53 v29.8,21.4 | v30.6,38.75 26.25,38.75 25.7,39.3 14.7,39.3 14.45,39.05 CPU.26
  Bottom 0.178: v29.8,21.4 30.2,21.8 30.2,32.6 29.3,33.5 29.3,37.45 v30.6,38.75
TCK  (via drill 0.6)
  Top 0.178: CPU.2 22.8,27.55 24.9,25.45 25.5,25.45 v25.7,25.25
  Bottom 0.178: v25.7,25.25 25.5,25.45 24.95,25.45 19.6,30.8 19.6,48.7 18.75,49.55 18.75,50.05 19.6,50.9 19.6,51.3 16.85,54.05 14.65,54.05 14.1,53.5 14.1,52.6 13.75,52.25 JP2.4
XIN0
  Top 0.178: U$3.P$2 3.85,33.25 4.05,33.05 4.05,32.6 4.3,32.35 C5.1 6.3,32.35 7.1,31.55 CPU.39
XOUT0
  Top 0.178: U$3.P$1 3.8,29.15 4.05,29.4 4.05,29.85 4.25,30.05 C6.1 6.15,30.05 7.15,31.05 CPU.40

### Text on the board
tPlace: USB Controller | Pat Pannuto | Eric Wustrow | Rev 1.0 | 8/24/2011 | TMS | TDO | TDI | TCK | GND | B | A | 2 | P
